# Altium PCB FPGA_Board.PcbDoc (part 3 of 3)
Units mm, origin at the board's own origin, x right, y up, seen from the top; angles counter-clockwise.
Board outline 130 x 90 mm, 4 copper layers (Component Side, Signal Layer 1, Signal Layer 2, Bottom Layer), stack 0.651 mm thick; 303 components, 175 nets, 968 pads, 775 vias.
Unrouted connection lines stored in the file: 193.
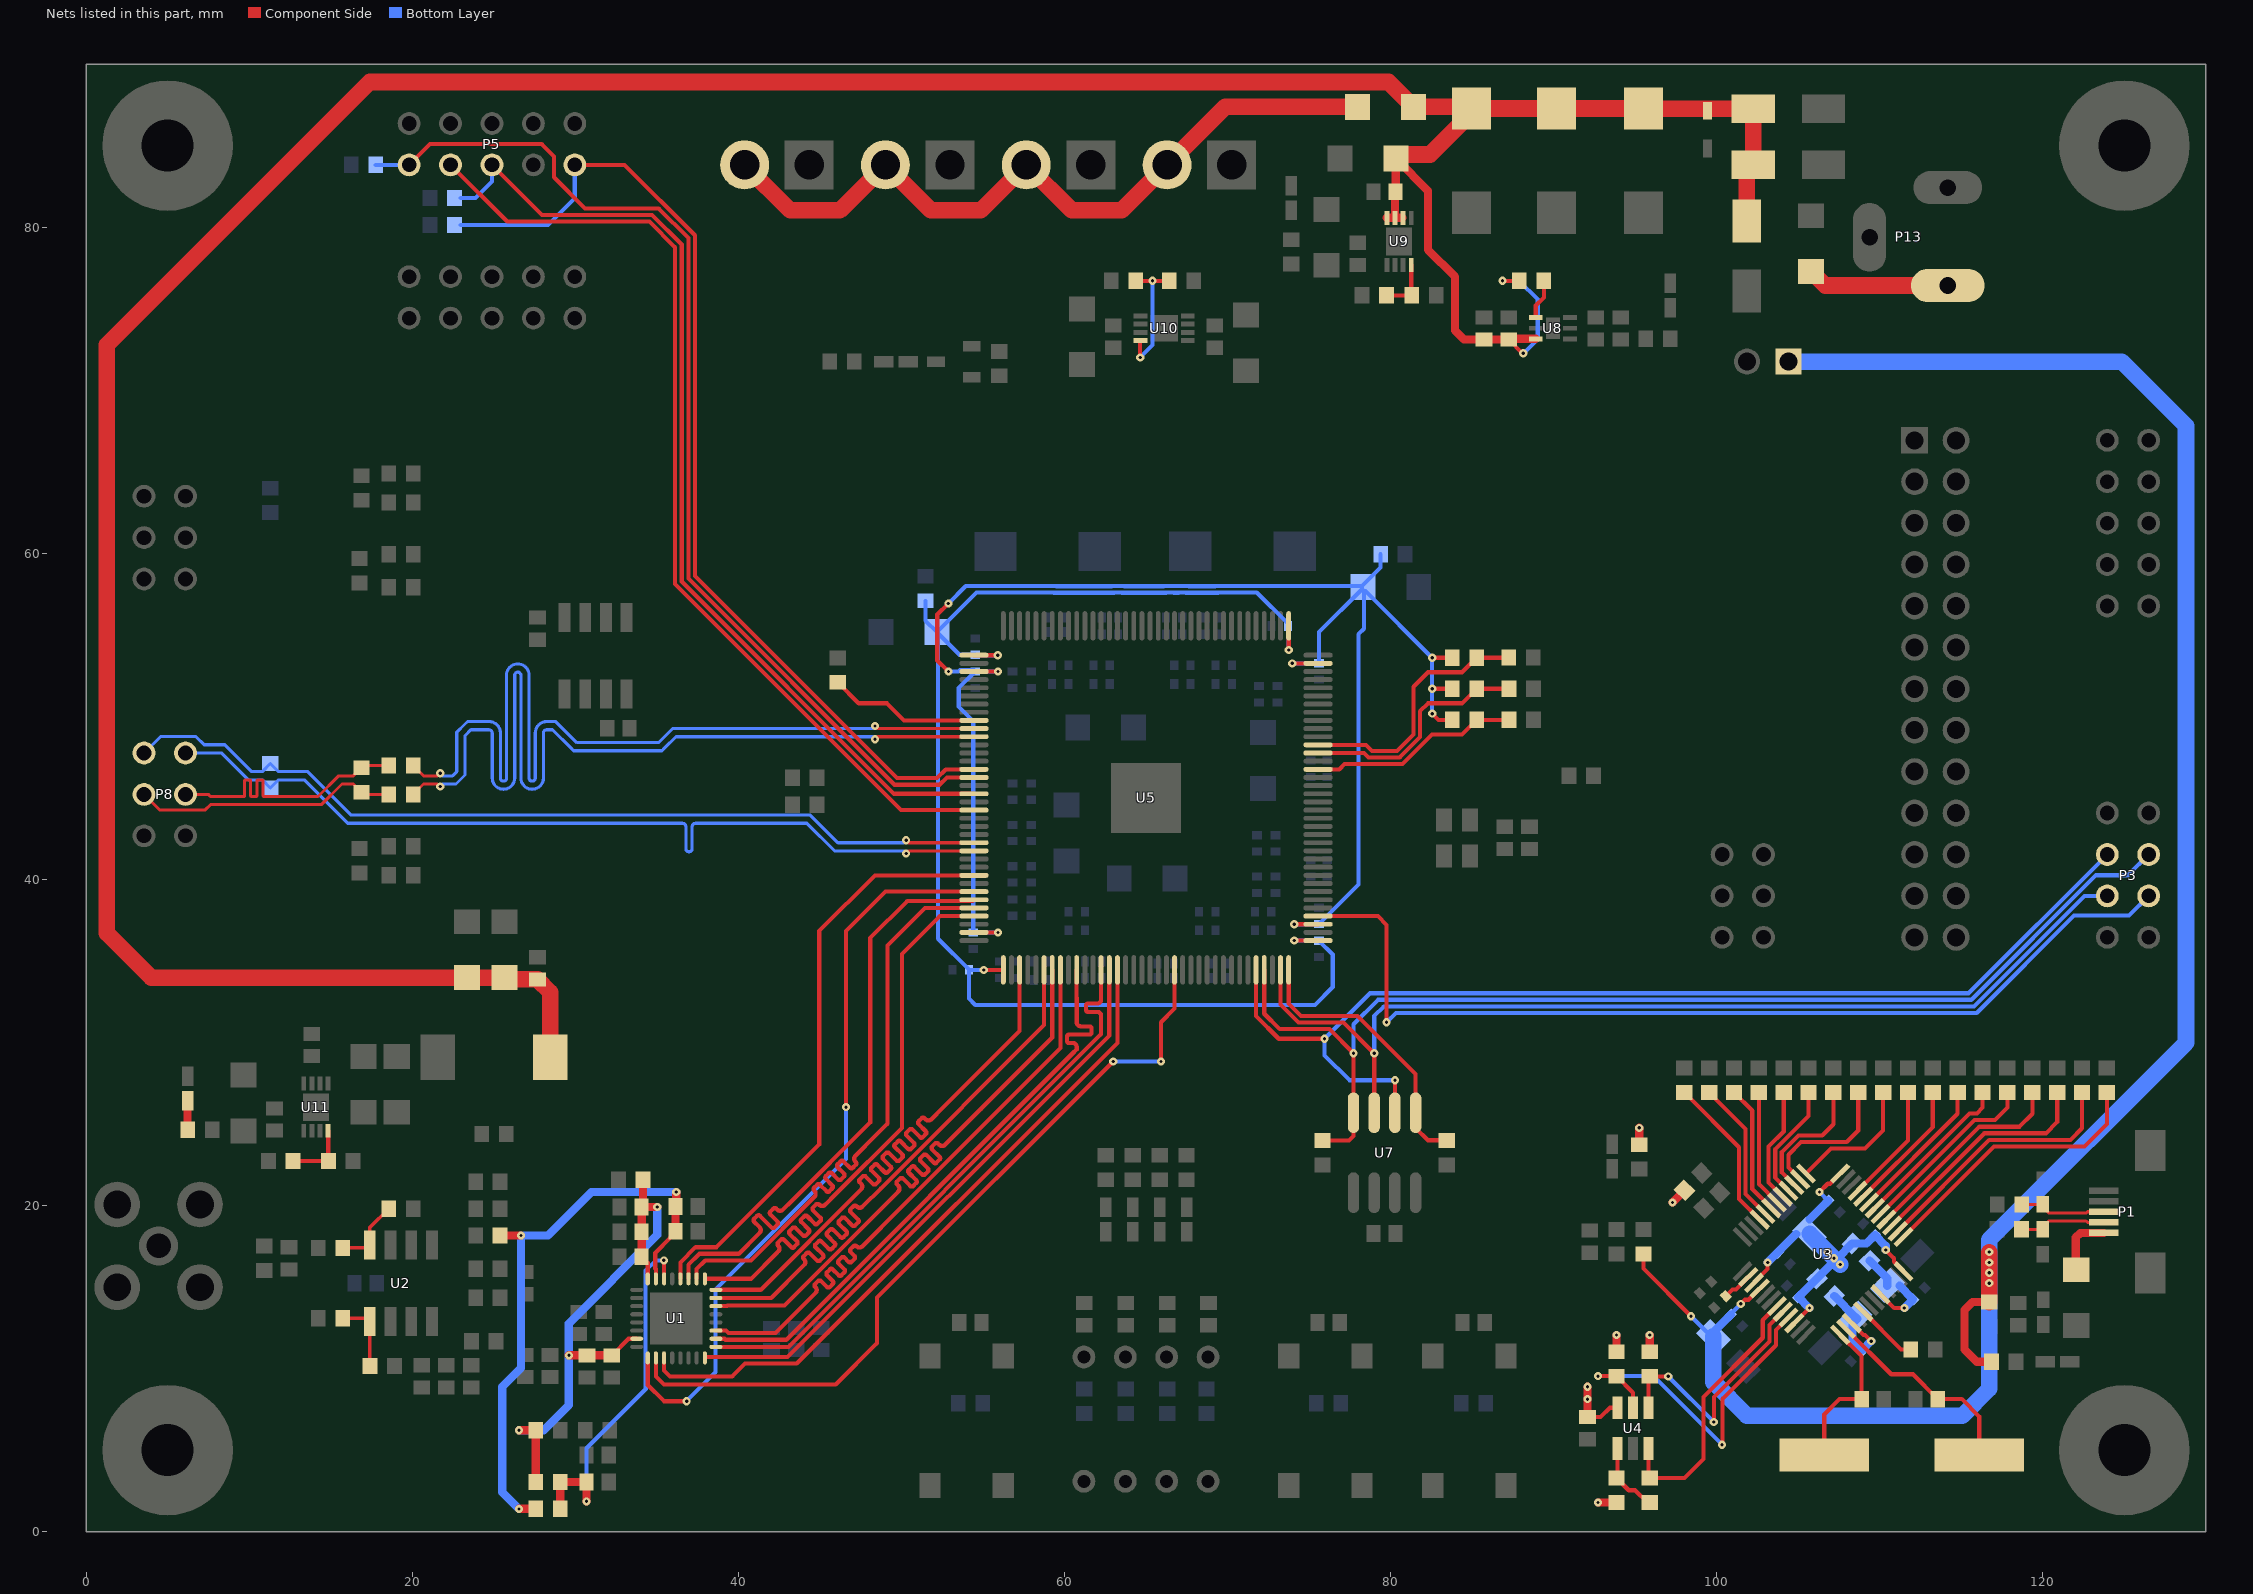
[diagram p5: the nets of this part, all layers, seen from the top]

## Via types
v1: diameter 0.5, hole 0.2, Component Side to Bottom Layer, 759 vias
v2: diameter 0.66, hole 0.33, Component Side to Bottom Layer, tented top, 16 vias

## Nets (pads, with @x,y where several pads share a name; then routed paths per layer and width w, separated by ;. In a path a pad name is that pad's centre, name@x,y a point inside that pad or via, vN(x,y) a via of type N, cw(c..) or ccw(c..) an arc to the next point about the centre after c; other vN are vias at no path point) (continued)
NetD17_1: D17.1 R94.1 | length 1.8
  Component Side w0.508: D17.1@6.223,26.428 6.223,24.65 R94.1@6.235,24.638
NetF1_1: F1.1 P1.1 | length 3.2
  Component Side w0.508: F1.1@122.014,16.696 122.014,18.034 122.298,18.318 P1.1@123.736,18.318
NetF2_2: F2.2 P11.2 P12.2 P14.2 P15.2 | length 46.1
  Component Side w1.016: P15.2@40.386,83.82 43.18,81.026 46.228,81.026 P14.2@49.022,83.82 51.816,81.026 54.864,81.026 P12.2@57.658,83.82 60.452,81.026 63.5,81.026 P11.2@66.294,83.82 69.85,87.376 F2.2@77.978,87.376 ; P12.2@58.143,83.742 P12.2@58.143,83.797
NetF3_1: F3.1 P13.1 | length 8.7
  Component Side w1.016: F3.1@105.791,77.284 106.652,76.423 P13.1@114.173,76.423
NetR1_1: R1.1 R4.2 U2.1 | length 4.5
  Component Side w0.22: R4.2@15.736,13.081 17.218,13.081 U2.1@17.399,12.9 17.399,10.172 R1.1@17.411,10.16
NetR6_2: R6.2 R8.1 U2.8 | length 4.4
  Component Side w0.22: R6.2@15.736,17.399 17.218,17.399 U2.8@17.399,17.58 17.399,18.657 R8.1@18.554,19.812
NetR18_2: R18.2 U3.5 | length 3.9
  Component Side w0.254: U3.5@108.986,13.491 111.301,11.176 R18.2@111.899,11.176
NetR19_1: R19.1 R22.1 U4.1 | length 4.5
  Component Side w0.254: U4.1@93.919,5.1 93.919,3.356 R19.1@93.853,3.29 94.603,2.54 94.996,2.54 95.746,1.79 R22.1@95.885,1.79
NetR20_1: R20.1 U3.44 U4.4 | length 15.7
  Component Side w0.254: U4.4@95.819,7.6 95.819,9.471 R20.1@95.885,9.537 95.897,9.525 v1(97.028,9.525) ; v1(99.822,6.731) 99.822,8.255 103.228,11.661 103.228,12.665 U3.44@104.054,13.491
  Bottom Layer w0.254: v1@97.155,9.525 v1(97.028,9.525) v1(99.822,6.731)
NetR21_1: R21.1 U3.45 U4.5 | length 22.3
  Component Side w0.254: v1(92.722,9.537) R21.1@93.853,9.537 94.869,8.521 U4.5@94.869,7.6 ; v1(100.33,5.334) 100.349,5.353 100.349,8.147 103.632,11.43 103.632,12.362 U3.45@104.407,13.137
  Bottom Layer w0.254: v1(92.722,9.537) 96.127,9.537 v1(100.33,5.334)
NetR22_2: R22.2 U3.43 U4.3 | length 16.9
  Component Side w0.254: U4.3@95.819,5.1 95.819,3.356 R22.2@95.885,3.29 98.032,3.29 99.187,4.445 99.187,8.255 102.824,11.892 102.824,12.968 U3.43@103.7,13.845
NetR28_1: R28.1 R34.2 U5.94 | length 13
  Component Side w0.254: U5.94@75.55,46.75 76.849,46.75 77.17,47.071 80.726,47.071 82.55,48.895 84.388,48.895 R28.1@85.277,49.784 R34.2@87.261,49.784
NetR29_1: R29.1 R35.2 U5.96 | length 14.5
  Component Side w0.254: U5.96@75.55,47.75 78.361,47.75 78.636,47.475 80.558,47.475 81.811,48.728 81.811,50.315 82.296,50.8 84.388,50.8 R29.1@85.277,51.689 R35.2@87.261,51.689
NetR30_1: R30.1 R36.2 U5.97 | length 15.9
  Component Side w0.254: U5.97@75.55,48.25 78.496,48.25 78.867,47.879 80.391,47.879 81.407,48.895 81.407,51.816 82.296,52.705 84.388,52.705 R30.1@85.277,53.594 87.223,53.594 R36.2@87.242,53.613
NetR41_2: R41.2 U3.33 | length 9.7
  Component Side w0.254: R41.2@98.011,26.936 101.371,23.576 101.371,20.399 U3.33@102.639,19.131
NetR42_2: R42.2 U3.32 | length 8.9
  Component Side w0.254: R42.2@99.535,26.936 101.775,24.696 101.775,20.702 U3.32@102.993,19.484
NetR43_2: R43.2 U3.31 | length 8
  Component Side w0.254: R43.2@101.059,26.936 102.179,25.816 102.179,21.005 U3.31@103.347,19.838
NetR44_2: R44.2 U3.30 | length 7.2
  Component Side w0.254: R44.2@102.583,26.936 102.583,21.309 U3.30@103.7,20.191
NetR45_2: R45.2 U3.29 | length 7.1
  Component Side w0.254: U3.29@104.054,20.545 103.182,21.417 103.182,23.616 104.108,24.543 104.107,24.544 R45.2@104.107,26.936
NetR51_2: R51.2 U3.28 | length 7.2
  Component Side w0.254: U3.28@104.407,20.899 103.586,21.72 103.586,23.449 105.631,25.494 R51.2@105.631,26.936
NetR54_2: R54.2 U3.27 | length 8.2
  Component Side w0.254: U3.27@104.761,21.252 103.99,22.023 103.99,23.281 105.012,24.303 106.472,24.303 107.155,24.986 R54.2@107.155,26.936
NetR55_2: R55.2 U3.26 | length 9
  Component Side w0.254: U3.26@105.114,21.606 104.394,22.326 104.394,23.114 105.179,23.899 107.973,23.899 108.679,24.605 R55.2@108.679,26.936
NetR56_2: R56.2 U3.25 | length 8.2
  Component Side w0.254: U3.25@105.468,21.959 107.004,23.495 109.093,23.495 110.203,24.605 R56.2@110.203,26.936
NetR61_2: R61.2 U3.21 | length 7.3
  Component Side w0.254: U3.21@108.633,20.899 111.727,23.993 R61.2@111.727,26.936
NetR66_2: R66.2 U3.20 | length 8.2
  Component Side w0.254: U3.20@108.986,20.545 113.251,24.81 R66.2@113.251,26.936
NetR67_2: R67.2 U3.19 | length 9
  Component Side w0.254: U3.19@109.34,20.191 114.775,25.627 R67.2@114.775,26.936
NetR68_2: R68.2 U3.18 | length 10.1
  Component Side w0.254: U3.18@109.693,19.838 115.51,25.654 115.951,25.654 116.299,26.002 R68.2@116.299,26.936
NetR71_2: R71.2 U3.17 | length 11.4
  Component Side w0.254: U3.17@110.047,19.484 115.801,25.238 117.059,25.238 117.823,26.002 R71.2@117.823,26.936
NetR75_2: R75.2 U3.16 | length 13
  Component Side w0.254: U3.16@110.401,19.131 116.104,24.834 118.56,24.834 119.355,25.629 R75.2@119.355,26.936
NetR78_2: R78.2 U3.15 | length 14.6
  Component Side w0.254: U3.15@110.754,18.777 116.407,24.43 120.188,24.43 120.879,25.121 R78.2@120.879,26.936
NetR79_2: R79.2 U3.14 | length 16.1
  Component Side w0.254: U3.14@111.108,18.424 116.71,24.026 121.689,24.026 122.403,24.74 R79.2@122.403,26.936
NetR80_2: R80.2 U3.13 | length 17.3
  Component Side w0.254: U3.13@111.461,18.07 117.013,23.622 122.555,23.622 123.927,24.994 R80.2@123.927,26.936
NetR86_1: R86.1 U8.4 | length 2.5
  Component Side w0.254: U8.4@88.9,74.452 88.9,75.184 89.408,75.692 89.408,76.696 R86.1@89.396,76.708
NetR89_1: R89.1 R91.2 U9.8 | length 3.4
  Component Side w0.254: R89.1@79.744,75.819 R91.2@81.292,75.819 81.268,75.843 U9.8@81.268,77.671
NetR90_1: R90.1 R92.2 U10.8 | length 8.1
  Component Side w0.254: R90.1@64.377,76.708 v1(65.405,76.708) R92.2@66.433,76.708 ; v1(64.643,72.009) 64.643,73.028 U10.8@64.664,73.049
  Bottom Layer w0.254: v1(64.643,72.009) 65.405,72.771 v1(65.405,76.708)
NetR95_1: R95.1 R96.2 U11.8 | length 4
  Component Side w0.254: R95.1@12.688,22.733 14.823,22.733 14.847,22.757 U11.8@14.847,24.585
NetU1_9: U1.9 U5.30 | length 46.2
  Component Side w0.254: U1.9@34.445,10.656 34.445,8.989 35.433,8.001 v1(36.83,8.001) ; v1(46.609,26.035) 46.609,36.83 49.029,39.25 U5.30@54.45,39.25
  Bottom Layer w0.254: v1(36.83,8.001) 38.608,9.779 38.608,14.859 46.609,22.86 v1(46.609,26.035)
NetU1_10: U1.10 U5.58 | length 48.1
  Component Side w0.254: U1.10@34.945,10.656 34.945,9.505 35.433,9.017 45.974,9.017 48.514,11.557 48.514,14.351 v1(62.992,28.829) ; v1(65.913,28.829) 65.913,31.242 66.75,32.079 U5.58@66.75,34.45
  Bottom Layer w0.254: v1(62.992,28.829) v1(65.913,28.829)
NetU1_11: U1.11 U5.51 | length 41.7
  Component Side w0.254: U1.11@35.445,10.656 35.445,9.894 35.814,9.525 39.624,9.525 40.405,10.306 43.58,10.306 63.25,29.976 U5.51@63.25,34.45
NetU1_16: U1.16 U5.50 | length 37
  Component Side w0.254: U1.16@37.945,10.656 37.999,10.71 43.025,10.71 62.75,30.435 U5.50@62.75,34.45
NetU1_17: U1.17 U5.49 | length 37
  Component Side w0.254: U1.17@38.62,11.331 43.075,11.331 62.25,30.506 62.25,31.496 62.25,31.623 ccw(c61.996,31.623) 61.996,31.877 61.451,31.877 cw(c61.451,32.004) 61.324,32.004 61.324,32.258 cw(c61.451,32.258) 61.451,32.385 61.996,32.385 ccw(c61.996,32.639) 62.25,32.639 62.25,33.274 U5.49@62.25,34.45
NetU1_18: U1.18 U5.46 | length 37
  Component Side w0.254: U1.18@38.62,11.831 39.147,11.831 39.209,11.769 42.941,11.769 60.509,29.337 60.75,29.578 60.75,29.718 ccw(c60.496,29.718) 60.496,29.972 60.281,29.972 cw(c60.281,30.099) 60.154,30.099 60.154,30.353 cw(c60.281,30.353) 60.281,30.48 61.525,30.48 ccw(c61.525,30.607) 61.652,30.607 61.652,30.861 ccw(c61.525,30.861) 61.525,30.988 61.004,30.988 cw(c61.004,31.242) 60.75,31.242 60.75,32.385 60.75,32.722 60.742,32.73 60.742,34.442 U5.46@60.75,34.45
NetU1_19: U1.19 U5.44 | length 37.3
  Component Side w0.254: U1.19@38.62,12.331 39.248,12.331 39.406,12.173 42.272,12.173 44.64,14.541 44.73,14.631 ccw(c44.551,14.811) 44.73,14.991 44.714,15.007 cw(c44.804,15.097) 44.714,15.187 44.893,15.366 cw(c44.983,15.276) 45.073,15.366 45.43,15.009 ccw(c45.52,15.099) 45.61,15.009 45.79,15.189 ccw(c45.7,15.278) 45.79,15.368 45.432,15.725 cw(c45.522,15.815) 45.432,15.905 45.612,16.085 cw(c45.702,15.995) 45.792,16.085 46.149,15.727 ccw(c46.239,15.817) 46.328,15.727 46.508,15.907 ccw(c46.418,15.997) 46.508,16.087 46.151,16.444 cw(c46.241,16.534) 46.151,16.623 46.33,16.803 cw(c46.42,16.713) 46.51,16.803 46.764,16.549 ccw(c46.854,16.638) 46.944,16.549 47.124,16.728 ccw(c47.034,16.818) 47.124,16.908 46.886,17.146 cw(c46.975,17.236) 46.886,17.325 47.065,17.505 cw(c47.155,17.415) 47.245,17.505 ; 47.245,17.505 ccw(c47.424,17.685) 47.604,17.505 ; 47.604,17.505 49.974,19.875 59.75,29.651 U5.44@59.75,34.45
NetU1_22: U1.22 U5.43 | length 37
  Component Side w0.254: U1.22@38.62,13.831 39.307,13.831 39.345,13.868 42.824,13.868 49.721,20.764 49.81,20.854 ccw(c49.631,21.034) 49.81,21.214 49.73,21.293 cw(c49.82,21.383) 49.73,21.473 49.91,21.653 cw(c50,21.563) 50.09,21.653 50.545,21.197 ccw(c50.635,21.287) 50.725,21.197 50.904,21.377 ccw(c50.815,21.467) 50.904,21.556 50.449,22.012 cw(c50.539,22.102) 50.449,22.191 50.628,22.371 cw(c50.718,22.281) 50.808,22.371 51.264,21.916 ccw(c51.353,22.005) 51.443,21.916 51.623,22.095 ccw(c51.533,22.185) 51.623,22.275 51.167,22.73 cw(c51.257,22.82) 51.167,22.91 51.347,23.089 cw(c51.437,23) 51.526,23.089 51.982,22.634 ccw(c52.072,22.724) 52.162,22.634 52.341,22.814 ccw(c52.251,22.903) 52.341,22.993 51.886,23.449 cw(c51.975,23.539) 51.886,23.628 52.065,23.808 cw(c52.155,23.718) 52.245,23.808 52.325,23.728 ccw(c52.504,23.908) 52.684,23.728 ; 52.684,23.728 54.864,25.908 59.25,30.294 U5.43@59.25,34.45
NetU1_23: U1.23 U5.42 | length 37.2
  Component Side w0.254: U1.23@38.62,14.331 42.017,14.331 43.942,16.256 44.032,16.346 ccw(c43.852,16.525) 44.032,16.705 44.015,16.721 cw(c44.105,16.811) 44.015,16.901 44.195,17.081 cw(c44.285,16.991) 44.375,17.081 44.83,16.625 ccw(c44.92,16.715) 45.01,16.625 45.189,16.805 ccw(c45.1,16.895) 45.189,16.984 44.734,17.44 cw(c44.824,17.53) 44.734,17.619 44.913,17.799 cw(c45.003,17.709) 45.093,17.799 45.549,17.344 ccw(c45.638,17.433) 45.728,17.344 45.908,17.523 ccw(c45.818,17.613) 45.908,17.703 45.452,18.158 cw(c45.542,18.248) 45.452,18.338 45.632,18.517 cw(c45.722,18.428) 45.811,18.517 46.267,18.062 ccw(c46.357,18.152) 46.447,18.062 46.626,18.242 ccw(c46.536,18.331) 46.626,18.421 46.171,18.877 cw(c46.26,18.967) 46.171,19.056 46.35,19.236 cw(c46.44,19.146) 46.53,19.236 46.985,18.78 ccw(c47.075,18.87) 47.165,18.78 47.345,18.96 ccw(c47.255,19.05) 47.345,19.14 46.889,19.595 cw(c46.979,19.685) 46.889,19.775 47.069,19.954 cw(c47.158,19.865) 47.248,19.954 47.265,19.938 ccw(c47.444,20.118) 47.624,19.938 48.768,21.082 58.75,31.064 U5.42@58.75,34.45
NetU1_24: U1.24 U5.39 | length 37.4
  Component Side w0.254: U1.24@38.62,14.831 41.374,14.831 47.434,20.892 47.524,20.981 ccw(c47.345,21.161) 47.524,21.341 47.444,21.42 cw(c47.534,21.51) 47.444,21.6 47.624,21.78 cw(c47.714,21.69) 47.804,21.78 48.259,21.324 ccw(c48.349,21.414) 48.439,21.324 48.618,21.504 ccw(c48.529,21.594) 48.618,21.683 48.163,22.139 cw(c48.253,22.229) 48.163,22.318 48.342,22.498 cw(c48.432,22.408) 48.522,22.498 48.978,22.043 ccw(c49.067,22.132) 49.157,22.043 49.337,22.222 ccw(c49.247,22.312) 49.337,22.402 48.881,22.857 cw(c48.971,22.947) 48.881,23.037 49.061,23.216 cw(c49.151,23.127) 49.24,23.216 49.696,22.761 ccw(c49.786,22.851) 49.876,22.761 50.055,22.941 ccw(c49.965,23.03) 50.055,23.12 49.6,23.576 cw(c49.689,23.666) 49.6,23.755 49.779,23.935 cw(c49.869,23.845) 49.959,23.935 50.414,23.479 ccw(c50.504,23.569) 50.594,23.479 50.774,23.659 ccw(c50.684,23.749) 50.774,23.839 50.318,24.294 cw(c50.408,24.384) 50.318,24.474 50.498,24.653 cw(c50.587,24.564) 50.677,24.653 51.133,24.198 ccw(c51.223,24.288) 51.312,24.198 51.492,24.377 ccw(c51.402,24.467) 51.492,24.557 51.059,24.99 cw(c51.149,25.08) 51.059,25.169 51.239,25.349 cw(c51.329,25.259) 51.418,25.349 51.476,25.292 ccw(c51.655,25.471) 51.835,25.292 52.514,25.971 57.25,30.707 U5.39@57.25,34.45
NetU1_25: U1.25 U5.33 | length 37.2
  Component Side w0.254: U1.25@37.945,15.506 40.779,15.506 42.355,17.081 42.444,17.171 ccw(c42.265,17.351) 42.444,17.531 42.428,17.547 cw(c42.518,17.637) 42.428,17.727 42.607,17.906 cw(c42.697,17.816) 42.787,17.906 43.243,17.451 ccw(c43.332,17.54) 43.422,17.451 43.602,17.63 ccw(c43.512,17.72) 43.602,17.81 43.146,18.265 cw(c43.236,18.355) 43.146,18.445 43.326,18.625 cw(c43.416,18.535) 43.506,18.625 43.961,18.169 ccw(c44.051,18.259) 44.141,18.169 44.32,18.349 ccw(c44.23,18.438) 44.32,18.528 43.865,18.984 cw(c43.955,19.074) 43.865,19.163 44.044,19.343 cw(c44.134,19.253) 44.224,19.343 44.679,18.887 ccw(c44.769,18.977) 44.859,18.887 45.039,19.067 ccw(c44.949,19.157) 45.039,19.247 44.583,19.702 cw(c44.673,19.792) 44.583,19.882 44.763,20.061 cw(c44.853,19.972) 44.942,20.061 44.959,20.045 ccw(c45.138,20.225) 45.318,20.045 ; 45.318,20.045 45.974,20.701 50.038,24.765 50.038,35.433 52.355,37.75 U5.33@54.45,37.75
NetU1_26: U1.26 U5.32 | length 37.2
  Component Side w0.254: U1.26@37.445,15.506 37.445,16.109 37.973,16.637 40.767,16.637 44.577,20.447 44.667,20.537 ccw(c44.487,20.716) 44.667,20.896 44.65,20.912 cw(c44.74,21.002) 44.65,21.092 44.83,21.272 cw(c44.92,21.182) 45.01,21.272 45.402,20.88 ccw(c45.491,20.969) 45.581,20.88 45.761,21.059 ccw(c45.671,21.149) 45.761,21.239 45.369,21.631 cw(c45.459,21.721) 45.369,21.81 45.548,21.99 cw(c45.638,21.9) 45.728,21.99 46.12,21.598 ccw(c46.21,21.688) 46.3,21.598 46.479,21.778 ccw(c46.389,21.867) 46.479,21.957 46.087,22.349 cw(c46.177,22.439) 46.087,22.529 46.267,22.708 cw(c46.357,22.619) 46.446,22.708 46.838,22.316 ccw(c46.928,22.406) 47.018,22.316 47.198,22.496 ccw(c47.108,22.586) 47.198,22.676 47.181,22.692 cw(c47.361,22.872) 47.181,23.051 48.45,24.32 49.149,25.019 49.149,35.941 51.458,38.25 U5.32@54.45,38.25
NetU1_27: U1.27 U5.31 | length 37.1
  Component Side w0.254: U1.27@36.945,15.506 36.945,16.371 37.615,17.041 40.028,17.041 41.212,18.224 41.301,18.314 ccw(c41.122,18.494) 41.301,18.674 40.967,19.007 cw(c41.057,19.097) 40.967,19.187 41.147,19.367 cw(c41.237,19.277) 41.327,19.367 42.036,18.657 ccw(c42.126,18.747) 42.216,18.657 42.395,18.837 ccw(c42.306,18.927) 42.395,19.016 41.965,19.447 cw(c42.055,19.536) 41.965,19.626 42.145,19.806 cw(c42.234,19.716) 42.324,19.806 42.379,19.751 ccw(c42.559,19.931) 42.738,19.751 43.243,20.256 48.087,25.1 48.087,36.403 50.361,38.677 54.377,38.677 U5.31@54.45,38.75
NetU1_28: U1.28 U5.28 | length 36.5
  Component Side w0.254: U1.28@36.445,15.506 36.445,16.506 37.384,17.445 38.654,17.445 44.958,23.749 44.958,36.83 48.378,40.25 U5.28@54.45,40.25
nSTATUS: R33.1 U5.9 | length 9.3
  Component Side w0.254: R33.1@46.101,52.082 47.383,50.8 49.115,50.8 50.165,49.75 U5.9@54.45,49.75
Ready_N: R52.1 U5.10 | length 58.8
  Component Side w0.19: R52.1@20.054,46.99 20.693,46.351 21.562,46.351 v1(21.717,46.506) ; v1(48.387,49.405) 48.542,49.25 U5.10@54.45,49.25
  Bottom Layer w0.19: v1(21.717,46.506) 21.872,46.351 22.479,46.351 22.733,46.605 22.733,49.022 23.241,49.53 23.387,49.676 24.716,49.676 cw(c24.716,48.986) 25.406,48.986 25.406,46.216 ccw(c25.596,46.216) 25.596,46.026 ccw(c25.596,46.216) 25.786,46.216 25.786,52.525 cw(c26.476,52.525) 26.476,53.215 cw(c26.476,52.525) 27.166,52.525 27.166,46.216 ccw(c27.356,46.216) 27.356,46.026 ccw(c27.356,46.216) 27.546,46.216 27.546,48.986 cw(c28.236,48.986) 28.236,49.676 28.81,49.676 30.099,48.387 35.107,48.387 35.97,49.25 48.232,49.25 v1(48.387,49.405)
Ready_P: R46.1 U5.11 | length 58.8
  Component Side w0.19: R46.1@20.054,45.212 20.693,45.851 21.562,45.851 v1(21.717,45.696) ; v1(48.387,48.595) 48.542,48.75 U5.11@54.45,48.75
  Bottom Layer w0.19: v1(21.717,45.696) 21.872,45.851 22.686,45.851 23.233,46.398 23.233,48.815 23.595,49.176 24.716,49.176 cw(c24.716,48.986) 24.906,48.986 24.906,46.216 ccw(c25.596,46.216) 25.596,45.526 ccw(c25.596,46.216) 26.286,46.216 26.286,52.525 cw(c26.476,52.525) 26.476,52.715 cw(c26.476,52.525) 26.666,52.525 26.666,46.216 ccw(c27.356,46.216) 27.356,45.526 ccw(c27.356,46.216) 28.046,46.216 28.046,48.986 cw(c28.236,48.986) 28.236,49.176 28.602,49.176 29.745,48.033 29.892,47.887 35.314,47.887 35.46,48.033 36.177,48.75 48.232,48.75 v1(48.387,48.595)
Ready_R_N: P8.4 R49.1 R52.2 | length 17.1
  Component Side w0.19: P8.4@6.096,45.212 7.493,45.212 7.62,45.085 9.525,45.085 9.658,45.085 ccw(c9.658,45.142) 9.715,45.142 9.715,46.028 cw(c9.772,46.028) 9.772,46.085 10.038,46.085 cw(c10.038,46.028) 10.095,46.028 10.095,45.142 ccw(c10.152,45.142) 10.152,45.085 10.418,45.085 ccw(c10.418,45.142) 10.475,45.142 10.475,46.028 cw(c10.532,46.028) 10.532,46.085 10.798,46.085 cw(c10.798,46.028) 10.855,46.028 10.855,45.142 ccw(c10.912,45.142) 10.912,45.085 10.922,45.085 14.224,45.085 15.49,46.351 16.391,46.351 R49.1@16.891,46.851 17.03,46.99 R52.2@18.554,46.99
Ready_R_P: P8.3 R46.2 R49.2 | length 16.3
  Component Side w0.19: P8.3@3.556,45.212 4.501,44.267 7.31,44.267 7.628,44.585 14.431,44.585 15.697,45.851 16.391,45.851 R49.2@16.891,45.351 17.03,45.212 R46.2@18.554,45.212
SENSE: C22.1 R12.1 R13.1 U1.30 | length 22.6
  Component Side w0.254: v1(35.433,16.637) 35.445,16.625 U1.30@35.445,15.506
  Component Side w0.508: R13.1@29.071,1.397 R12.1@29.071,3.048 C22.1@30.689,3.048 v1(30.689,1.86)
  Bottom Layer w0.254: v1(30.689,1.86) 30.689,5.115 34.32,8.746 34.32,10.264 34.313,10.271 34.313,16.007 34.943,16.637 v1(35.433,16.637)
SPI-CLK: P3.3 U5.68 U7.2 | length 68.3
  Component Side w0.254: U5.68@71.75,34.45 71.75,31.618 73.142,30.226 v1(75.946,30.226) ; U7.2@80.264,25.691 v1(80.264,27.686)
  Bottom Layer w0.254: v1(80.264,27.686) 77.47,27.686 75.946,29.21 v1(75.946,30.226) 78.74,33.02 115.443,33.02 P3.3@123.952,41.529
SPI-CS0: R83.2 U5.72 U7.1 | length 17.2
  Component Side w0.254: U5.72@73.75,34.45 73.75,32.389 74.516,31.623 77.978,31.623 81.534,28.067 U7.1@81.534,25.691 81.534,24.765 82.296,24.003 83.427,24.003 R83.2@83.439,23.991
SPI-CS1: P3.6 U5.76 | length 60.3
  Component Side w0.254: U5.76@75.55,37.75 79.217,37.75 79.756,37.211 v1(79.756,31.242)
  Bottom Layer w0.254: v1(79.756,31.242) 80.322,31.808 115.945,31.808 121.92,37.783 125.286,37.783 P3.6@126.492,38.989
SPI-MISO: P3.4 R84.2 U5.69 U7.4 | length 71.1
  Component Side w0.254: U5.69@72.25,34.45 72.25,31.763 73.198,30.815 76.246,30.815 v1(77.724,29.337) U7.4@77.724,25.691 77.724,24.257 77.458,23.991 R84.2@75.819,23.991
  Bottom Layer w0.254: v1(77.724,29.337) 77.724,31.115 79.225,32.616 115.61,32.616 123.253,40.259 125.222,40.259 P3.4@126.492,41.529
SPI-MOSI: P3.5 U5.71 U7.3 | length 63.1
  Component Side w0.254: U5.71@73.25,34.45 73.25,32.318 74.349,31.219 77.112,31.219 v1(78.994,29.337) U7.3@78.994,25.691
  Bottom Layer w0.254: v1(78.994,29.337) 78.994,31.623 79.583,32.212 115.778,32.212 122.555,38.989 P3.5@123.952,38.989
TCK: P5.1 R40.1 U5.16 | length 66.6
  Component Side w0.254: P5.1@19.812,83.82 21.082,85.09 27.94,85.09 28.702,84.328 28.702,83.058 30.607,81.153 35.116,81.153 36.934,79.335 36.934,58.442 49.571,45.805 52.345,45.805 52.79,46.25 U5.16@54.45,46.25
  Bottom Layer w0.254: R40.1@17.768,83.82 P5.1@19.812,83.82
TDI: P5.9 R39.1 U5.15 | length 62.3
  Component Side w0.254: P5.9@29.972,83.82 33.02,83.82 37.338,79.502 37.338,58.61 49.739,46.209 52.178,46.209 52.719,46.75 U5.15@54.45,46.75 U5.15@54.423,46.723
  Bottom Layer w0.254: R39.1@22.975,80.137 28.321,80.137 29.972,81.788 P5.9@29.972,83.82
TDO: P5.3 U5.20 | length 60.6
  Component Side w0.254: P5.3@22.352,83.82 25.827,80.345 34.544,80.345 36.126,78.763 36.126,58.108 49.984,44.25 U5.20@54.45,44.25
TMS: P5.5 R38.1 U5.18 | length 61
  Component Side w0.254: P5.5@24.892,83.82 27.963,80.749 34.712,80.749 36.53,78.931 36.53,58.275 49.555,45.25 U5.18@54.45,45.25
  Bottom Layer w0.254: R38.1@22.975,81.788 23.876,81.788 24.892,82.804 P5.5@24.892,83.82
TRG_N: P8.2 R48.1 U5.25 | length 54.6
  Component Side w0.19: v1(50.292,41.595) 50.447,41.75 U5.25@54.45,41.75
  Bottom Layer w0.19: P8.2@6.096,47.752 6.104,47.76 8.298,47.76 9.953,46.105 10.803,46.105 R48.1@11.303,45.605 11.803,46.105 13.386,46.105 16.049,43.442 36.195,43.442 36.39,43.442 36.585,43.442 cw(c36.585,43.247) 36.78,43.247 36.78,41.886 ccw(c36.975,41.886) 36.975,41.691 ccw(c36.975,41.886) 37.17,41.886 37.17,43.247 cw(c37.365,43.247) 37.365,43.442 37.592,43.442 44.202,43.442 45.894,41.75 50.137,41.75 v1(50.292,41.595)
TRG_P: P8.1 R48.2 U5.24 | length 54.6
  Component Side w0.19: v1(50.292,42.405) 50.447,42.25 U5.24@54.45,42.25
  Bottom Layer w0.19: P8.1@3.556,47.752 4.572,48.768 6.731,48.768 7.239,48.26 8.505,48.26 10.16,46.605 10.803,46.605 R48.2@11.303,47.105 11.803,46.605 13.593,46.605 13.716,46.482 16.256,43.942 44.409,43.942 46.101,42.25 50.137,42.25 v1(50.292,42.405)
USB_N: D1.2 P1.2 R16.1 | length 5.4
  Component Side w0.19: R16.1@118.688,18.542 119.505,18.542 119.507,18.54 D1.2@119.982,18.54 120.077,18.635 120.077,18.768 120.363,19.054 122.655,19.054 122.741,18.968 P1.2@123.736,18.968
USB_P: D2.2 P1.3 R17.1 | length 5.4
  Component Side w0.19: R17.1@118.7,20.066 119.505,20.066 119.507,20.068 D2.2@119.982,20.068 120.077,19.973 120.077,19.84 120.363,19.554 122.677,19.554 122.741,19.618 P1.3@123.736,19.618
VBUS: C23.1 C24.2 J1.1 L4.2 R23.2 R25.2 U3.40 | length 131.7
  Component Side w0.254: R25.2@95.504,17.03 95.504,16.129 v1(98.425,13.208) ; v1(101.473,13.97) 101.727,14.224 101.958,14.224 U3.40@102.639,14.905
  Component Side w0.508: L4.2@116.713,14.085 115.685,14.085 115.189,13.589 115.189,11.176 115.951,10.414 R23.2@116.852,10.414
  Component Side w1.016: L4.2@116.713,14.085 v1(116.713,15.24) v1(116.713,15.875) v1(116.713,16.51) v1(116.713,17.145)
  Bottom Layer w0.254: v1(98.425,13.208) 99.665,11.968 C23.1@99.792,11.968 ; C24.2@100.865,13.308 100.865,13.362 v1(101.473,13.97) v1@101.528,13.97
  Bottom Layer w0.508: C23.1@99.792,11.968 99.792,12.234 C24.2@100.865,13.308
  Bottom Layer w1.016: C23.1@99.792,11.968 99.792,9.174 101.854,7.112 115.062,7.112 116.713,8.763 v1(116.713,15.24) v1(116.713,15.875) v1(116.713,16.51) v1(116.713,17.145) 116.713,17.907 128.778,29.972 128.778,67.818 124.841,71.755 J1.1@104.394,71.755
VCC: C122.+ C123.+ C124.+ C125.2 C126.2 C129.2 C130.2 C137.2 C138.2 C139.2 D10.2 D11.2 D12.2 D14.2 F2.1 L8.1 R86.2 U8.6 U9.2 U9.3 U9.4 | length 219.3
  Component Side w0.254: v1(86.868,76.708) R86.2@87.896,76.708 ; C126.2@87.249,73.107 88.093,72.263 v1(88.138,72.263)
  Component Side w0.508: U9.4@79.768,80.571 U9.3@80.268,80.571 ; C129.2@80.323,84.201 80.323,82.183 C130.2@80.309,82.169 80.268,82.128 U9.3@80.268,80.571 ; C129.2@80.386,84.138 82.296,82.228 82.296,78.613 83.947,76.962 83.947,73.66 84.5,73.107 C125.2@85.725,73.107 C126.2@87.249,73.107 87.294,73.152 U8.6@88.9,73.152 ; U9.2@80.714,80.571 U9.3@80.268,80.571
  Component Side w1.016: L8.1@28.469,29.083 28.469,33.081 C139.2@27.686,33.864 25.767,33.864 C138.2@25.654,33.977 C137.2@23.368,33.977 3.996,33.977 1.27,36.703 1.27,72.771 17.399,88.9 79.874,88.9 F2.1@81.398,87.376 84.462,87.376 84.666,87.58 C124.+@84.97,87.884 ; C129.2@80.386,84.138 80.704,84.455 82.423,84.455 84.97,87.002 C124.+@84.97,87.276 ; C124.+@85.605,87.276 C123.+@90.177,87.276 C122.+@95.511,87.276 95.538,87.249 99.441,87.249 D14.2@101.482,87.249 ; D10.2@101.854,80.382 101.854,83.43 D11.2@102.244,83.82 D14.2@102.244,87.249
  Bottom Layer w0.254: v1(86.868,76.708) 87.884,76.708 89.027,75.565 89.027,73.152 v1(88.138,72.263)
VCC3V3: C28.1 C29.2 C34.2 C36.2 C37.2 C38.2 L3.2 L5.2 R15.2 R19.2 R20.2 R21.2 R24.2 U3.12 U3.24 U3.39 U3.46 U4.6 | length 31.9
  Component Side w0.254: C34.2@92.075,7.03 92.877,7.03 93.447,7.6 U4.6@93.919,7.6 ; U3.39@102.286,15.259 103.124,16.097 v1(103.124,16.51) ; U3.46@104.761,12.784 v1(105.693,13.716) ; v1(106.299,20.828) 106.807,21.336 106.949,21.336 U3.24@107.572,21.959 ; v1(110.363,17.272) 110.871,16.764 110.871,16.556 U3.12@111.461,15.966
  Component Side w0.508: C34.2@92.075,7.03 v1(92.075,8.128) v1(92.075,8.89) ; v1(92.722,1.79) R19.2@93.853,1.79 ; R21.2@93.853,11.037 v1(93.853,12.065) ; R24.2@95.25,23.737 v1(95.25,24.765) ; R20.2@95.885,11.037 v1(95.885,12.065) ; v1(97.282,20.193) R15.2@98.022,20.933
  Bottom Layer w0.254: v1(105.693,13.716) v1@105.791,13.716 ; v1(106.299,20.828) C37.2@106.834,20.293
  Bottom Layer w0.508: v1(103.124,16.51) C28.1@104.872,18.258 ; v1(105.693,13.716) 105.664,13.716 C38.2@105.002,14.378 106.266,15.643 L3.2@106.277,15.643 ; 105.694,19.152 C37.2@106.834,20.293 ; L3.2@106.15,15.516 L3.2@106.277,15.643 ; v1(110.363,17.272) 110.363,17.526 C36.2@109.701,18.188 109.187,17.675 L5.2@108.309,17.675 107.397,16.764 v1(107.188,16.764) 107.188,16.555 L3.2@106.277,15.643
  Bottom Layer w1.016: C28.1@105.694,18.258 v1(106.807,17.145) v1(107.188,16.764) v1(107.569,16.383)
VCC_PLL: C112.2 C115.2 C117.2 C119.2 C121.2 L6.2 U5.1 U5.37 U5.73 U5.109 | length 88.9
  Component Side w0.254: U5.1@54.45,53.75 v1(55.909,53.75) ; v1(55.052,34.45) U5.37@56.25,34.45 ; v1(73.75,54.065) U5.109@73.75,55.55 ; v1(74.096,36.25) U5.73@75.55,36.25
  Bottom Layer w0.254: L6.2@51.482,57.082 51.482,55.859 C112.2@52.176,55.165 ; v1(55.052,34.45) 54.155,34.45 C115.2@54.141,34.464 ; v1(55.909,53.75) 54.556,53.75 C119.2@54.53,53.776 53.565,53.776 C112.2@52.244,55.097 ; v1(73.75,54.065) 73.75,55.495 C117.2@73.699,55.546 73.699,55.681 71.791,57.589 69.417,57.589 69.406,57.578 67.451,57.578 67.44,57.589 67.004,57.589 66.993,57.578 66.705,57.578 66.686,57.597 66.25,57.597 66.231,57.578 63.514,57.578 63.503,57.589 63.067,57.589 63.056,57.578 59.339,57.578 59.328,57.589 54.6,57.589 C112.2@52.176,55.165 ; v1(74.096,36.25) 75.596,36.25 C121.2@75.612,36.234 76.454,35.392 76.454,33.401 75.358,32.305 54.53,32.305 54.141,32.694 C115.2@54.141,34.464 ; C112.2@52.176,55.165 C112.2@52.244,55.097 ; C112.2@52.244,55.097 52.244,36.361 C115.2@54.141,34.464
VCCA: C113.2 C114.2 C116.2 C118.2 C120.2 L7.1 R28.2 R29.2 R30.2 U5.3 U5.35 U5.75 U5.107 | length 104.3
  Component Side w0.254: v1(52.879,56.927) 52.197,56.245 52.197,53.434 v1(52.887,52.744) ; U5.35@54.45,36.75 v1(55.927,36.75) ; U5.3@54.45,52.75 v1(55.925,52.75) ; v1(73.971,53.25) U5.107@75.55,53.25 ; v1(74.096,37.25) U5.75@75.55,37.25 ; v1(82.55,50.165) 82.931,49.784 R28.2@83.777,49.784 ; v1(82.55,51.689) R29.2@83.777,51.689 ; v1(82.55,53.594) R30.2@83.777,53.594
  Bottom Layer w0.254: v1(52.879,56.927) 53.945,57.993 59.496,57.993 59.507,57.982 62.888,57.982 62.899,57.993 63.671,57.993 63.682,57.982 66.063,57.982 66.082,58.001 67.6,58.001 67.619,57.982 69.238,57.982 69.249,57.993 C113.2@78.242,57.993 ; v1(52.887,52.744) 53.506,52.744 53.594,52.832 54.454,52.832 C118.2@54.536,52.75 ; v1(55.925,52.75) C118.2@54.536,52.75 ; v1(55.927,36.75) 54.411,36.75 C114.2@54.403,36.742 54.403,49.704 53.514,50.593 53.514,51.728 C118.2@54.53,52.744 C118.2@54.536,52.75 ; v1(73.971,53.25) 75.61,53.25 C116.2@75.612,53.252 75.612,55.165 C113.2@78.242,57.795 ; v1(74.096,37.25) 75.596,37.25 C120.2@75.612,37.266 78.025,39.679 78.025,55.038 78.359,55.372 C113.2@78.359,57.678 ; L7.1@79.387,59.944 79.387,59.138 C113.2@78.242,57.993 ; v1(82.55,50.165) v1(82.55,51.689) v1(82.55,53.594) 78.466,57.678 C113.2@78.359,57.678 ; C113.2@78.242,57.795 C113.2@78.242,57.993 ; C113.2@78.242,57.795 C113.2@78.359,57.678
VCM: C10.2 C11.2 R2.2 R13.2 U1.31 | length 36.6
  Component Side w0.254: U1.31@34.945,15.506 34.945,16.109 34.906,16.148 34.906,17.096 35.842,18.032 35.842,18.107 C11.2@36.15,18.415
  Component Side w0.508: R2.2@25.388,18.161 v1(26.67,18.161) ; v1(26.543,1.397) R13.2@27.571,1.397 R13.2@27.698,1.397 ; C11.2@36.15,18.415 C10.2@36.15,19.939 36.195,19.984 v1(36.195,20.828)
  Bottom Layer w0.508: v1(26.543,1.397) 25.527,2.413 25.527,8.89 26.67,10.033 v1(26.67,18.161) 28.321,18.161 30.988,20.828 v1(36.195,20.828)
VCORE: C35.2 U3.38 | length 1.9
  Component Side w0.254: C35.2@100.557,14.451 100.965,14.859 101.179,14.859 U3.38@101.932,15.612
VDD: C1.1 C2.1 C4.1 C6.1 C9.1 L1.1 R11.2 R12.2 U1.7 U1.32 | length 34.3
  Component Side w0.254: C9.1@32.246,10.812 33.265,11.831 U1.7@33.77,11.831 ; C4.1@34.069,16.863 34.445,16.487 U1.32@34.445,15.506
  Component Side w0.508: v1(26.543,6.223) R11.2@27.571,6.223 R12.2@27.571,3.175 ; R12.2@27.571,2.794 27.571,2.921 R12.2@27.679,2.813 ; v1(29.608,10.812) C6.1@30.722,10.812 C9.1@32.246,10.812 ; C4.1@34.069,16.863 C2.1@34.069,18.387 C1.1@34.069,19.911 ; L1.1@34.151,21.59 34.151,19.993 C1.1@34.069,19.911 ; v1(35.024,19.911) C1.1@34.069,19.911
  Bottom Layer w0.508: v1(26.543,6.223) 28.067,6.223 29.608,7.764 v1(29.608,10.812) 29.608,12.772 35.024,18.188 v1(35.024,19.911)
VPHY: C25.1 C26.2 L3.1 U3.3 | length 6.9
  Component Side w0.254: U3.3@108.279,12.784 108.998,12.065 109.093,12.065 v1(109.474,11.684) v1@109.379,11.684
  Bottom Layer w0.254: v1@109.347,11.684 v1(109.474,11.684)
  Bottom Layer w0.508: L3.1@107.21,14.456 108.521,13.144 108.615,13.051 108.582,13.018 108.331,12.767 108.331,11.756 C26.2@108.939,11.149 v1(109.474,11.684)
VPLL: C30.1 C31.2 L5.1 U3.8 | length 5.7
  Component Side w0.254: U3.8@110.047,14.552 110.883,13.716 v1(111.506,13.716)
  Bottom Layer w0.508: L5.1@109.369,16.615 110.46,15.524 C30.1@110.46,15.083 ; C30.1@111.21,15.083 C31.2@112.041,14.251 v1(111.506,13.716)
XI: C39.2 U3.1 Y1.1 | length 9.7
  Component Side w0.254: Y1.1@106.596,4.699 106.596,7.188 107.536,8.128 C39.2@108.888,8.128 108.888,10.761 U3.1@107.572,12.077
XO: C40.2 U3.2 Y1.2 | length 12.8
  Component Side w0.254: U3.2@107.926,12.43 110.704,9.652 112.026,9.652 C40.2@113.55,8.128 115.029,8.128 116.096,7.061 Y1.2@116.096,4.699
pads on no net: P1.4 P5.6 P5.7 P5.8 U1.12 U1.13 U1.14 U1.15 U2.7 U5.101 U5.126 U5.127 U5.128 U5.129 U7.6 U7.7 U8.2 U8.5

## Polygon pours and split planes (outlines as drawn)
+3V3 on Signal Layer 2 "Signal2 Layer-+3V3" (solid, shelved, pour order 84): 0,90 130,90 130,0 0,0
+3V-A on Signal Layer 2 "Signal2 Layer-GND" (solid, shelved, pour order 76): 0,32.766 24.765,32.766 24.765,23.241 25.527,22.479 39.624,22.479 39.624,18.034 36.068,18.034 36.068,14.986 34.163,14.986 34.163,0 0,0
+2V5 on Signal Layer 2 "Signal2 Layer-+2V5" (solid, shelved, pour order 36): 84.455,78.105 98.425,78.105 98.425,70.485 87.63,70.485 87.63,59.182 81.153,59.182 81.153,60.833 84.455,60.833 84.455,71.12
+1V2 on Signal Layer 2 "Signal2 Layer-+1V2" (solid, shelved, pour order 28): 55.88,35.814 73.834,35.814 73.834,43.675 70.18,43.675 70.18,46.977 74.295,46.977 74.295,55.626 58.547,55.626 58.547,58.674 64.77,58.674 64.77,69.85 73.025,69.85 73.025,77.47 50.546,77.47 50.546,47.244 50.559,47.231 61.341,47.231 61.341,41.23 60.973,40.767 55.88,40.767
VCC3V3 on Signal Layer 2 "Signal2 Layer-+VCC3V3" (solid, shelved, pour order 40): 130,0 130,28.829 89.662,28.829 89.662,0
GND on Bottom Layer "BOT Layer-GND" (solid, shelved, pour order 80): 0,90 130,90 130,0 0,0
AGND on Bottom Layer "BOT Layer-AGND" (solid, shelved, pour order 72): 0,32.766 24.765,32.766 24.765,23.241 25.527,22.479 39.624,22.479 39.624,18.034 36.068,18.034 36.068,14.986 34.163,14.986 34.163,0 0,0
+3V3 on Bottom Layer "BOT Layer-+3V3" (solid, shelved, pour order 64): 70.993,62.611 77.343,62.611 77.343,57.404 70.993,57.404
+1V2 on Bottom Layer "BOT Layer-+1V2" (solid, shelved, pour order 62): 62.611,47.498 58.801,47.498 58.801,51.435 62.611,51.435
+1V2 on Bottom Layer "BOT Layer-+1V2" (solid, shelved, pour order 60): 61.595,41.91 61.595,38.354 64.77,38.354 64.77,41.91
+3V3 on Bottom Layer "BOT Layer-+3V3" (solid, shelved, pour order 58): 58.42,46.355 58.42,43.053 61.722,43.053 61.722,46.355
+3V3 on Bottom Layer "BOT Layer-+3V3" (solid, shelved, pour order 56): 73.914,46.863 73.914,43.815 70.104,43.815 70.104,46.863
+1V2 on Bottom Layer "BOT Layer-+1V2" (solid, shelved, pour order 38): 50.546,57.589 58.547,57.589 58.547,62.484 52.959,62.484 50.546,60.071
+1V2 on Bottom Layer "BOT Layer-+1V2" (solid, shelved, pour order 34): 65.024,41.783 65.024,38.227 61.722,38.227 61.722,41.783
+1V2 on Bottom Layer "BOT Layer-+1V2" (solid, shelved, pour order 32): 62.484,47.244 58.674,47.244 58.674,51.054 62.484,51.054
GND on Component Side "TOP Layer-GND" (solid, shelved, pour order 78): 0,90 130,90 130,0 0,0
AGND on Component Side "TOP Layer-GND" (solid, shelved, pour order 70): 0,32.766 24.765,32.766 24.765,23.241 25.527,22.479 39.624,22.479 39.624,18.034 36.068,18.034 36.068,14.986 34.163,14.986 34.163,0 0,0
GND on Signal Layer 1 "Signal1 Layer-GND" (solid, shelved, pour order 82): 0,90 130,90 130,0 0,0
AGND on Signal Layer 1 "Signal1 Layer-AGND" (solid, shelved, pour order 74): 0,32.766 24.765,32.766 24.765,23.241 25.527,22.479 39.624,22.479 39.624,18.034 36.068,18.034 36.068,14.986 34.163,14.986 34.163,0 0,0

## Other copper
Signal Layer 2:
  pour cut-out: 105.953,21.207 106.715,21.207 106.715,20.445 105.953,20.445
  pour cut-out: 110.017,17.651 110.779,17.651 110.779,16.889 110.017,16.889
  pour cut-out: 105.347,14.095 106.109,14.095 106.109,13.333 105.347,13.333
  pour cut-out: 102.778,16.889 103.54,16.889 103.54,16.127 102.778,16.127
  pour cut-out: 39.655,13.71 40.417,13.71 40.417,12.948 39.655,12.948
  pour cut-out: 40.675,13.714 41.437,13.714 41.437,12.952 40.675,12.952
  pour cut-out: 55.534,46.099 56.296,46.099 56.296,45.337 55.534,45.337
  pour cut-out: 55.534,52.129 56.296,52.129 56.296,51.367 55.534,51.367
  pour cut-out: 58.404,54.43 59.166,54.43 59.166,53.668 58.404,53.668
  pour cut-out: 59.344,54.354 60.106,54.354 60.106,53.592 59.344,53.592
  pour cut-out: 60.904,54.412 61.666,54.412 61.666,53.65 60.904,53.65
  pour cut-out: 62.904,54.358 63.666,54.358 63.666,53.596 62.904,53.596
  pour cut-out: 65.904,54.437 66.666,54.437 66.666,53.675 65.904,53.675
  pour cut-out: 66.904,54.421 67.666,54.421 67.666,53.659 66.904,53.659
  pour cut-out: 69.297,54.401 70.059,54.401 70.059,53.639 69.297,53.639
  pour cut-out: 70.059,54.401 70.821,54.401 70.821,53.639 70.059,53.639
  pour cut-out: 73.712,51.129 74.474,51.129 74.474,50.367 73.712,50.367
  pour cut-out: 73.64,46.629 74.402,46.629 74.402,45.867 73.64,45.867
  pour cut-out: 73.488,42.209 74.25,42.209 74.25,41.447 73.488,41.447
  pour cut-out: 73.671,40.629 74.433,40.629 74.433,39.867 73.671,39.867
  pour cut-out: 73.488,39.161 74.25,39.161 74.25,38.399 73.488,38.399
  pour cut-out: 72.298,36.447 73.06,36.447 73.06,35.685 72.298,35.685
  pour cut-out: 68.361,36.32 69.123,36.32 69.123,35.558 68.361,35.558
  pour cut-out: 67.472,36.32 68.234,36.32 68.234,35.558 67.472,35.558
  pour cut-out: 65.404,36.323 66.166,36.323 66.166,35.561 65.404,35.561
  pour cut-out: 60.904,36.356 61.666,36.356 61.666,35.594 60.904,35.594
  pour cut-out: 55.962,36.494 56.724,36.494 56.724,35.732 55.962,35.732
  pour cut-out: 55.581,38.018 56.343,38.018 56.343,37.256 55.581,37.256
  pour cut-out: 55.533,40.129 56.295,40.129 56.295,39.367 55.533,39.367
  pour cut-out: 55.636,41.629 56.398,41.629 56.398,40.867 55.636,40.867
  pour cut-out: 59.904,36.362 60.666,36.362 60.666,35.6 59.904,35.6
  pour cut-out: 57.404,36.322 58.166,36.322 58.166,35.56 57.404,35.56

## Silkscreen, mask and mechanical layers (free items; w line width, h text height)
Top Overlay:
  lines w0.22: 40.259,63.754 89.408,63.754
  lines w0.254: 0.508,22.098 8.128,22.098 9.506,20.72 17.164,20.72 19.304,22.86 48.26,22.86 48.26,0.762 ; 0.508,35.56 17.272,35.56 21.082,39.37 29.21,39.37 33.02,35.56 33.02,22.86 ; 39.37,73.66 44.704,68.326 96.266,68.326 99.695,71.755 99.695,79.629 ; 48.26,15.24 48.26,17.018 56.388,17.018 58.42,19.05 58.42,27.178 71.628,27.178 71.628,19.05 73.66,17.018 89.662,17.018 89.662,15.24 ; 89.662,0.508 89.662,30.48 129.032,30.48
  text "+3V3 OK" at 75.184,84.836 h0.8 r90
  text "JTAG" at 13.97,82.296 h1 r90
  text "POWER +5V" at 119.888,75.438 h1.3
  text "4x +5V Power Output" at 37.846,74.422 h1.2
  text "AS" at 13.97,74.168 h1 r90
  text "+1V2 OK" at 45.974,72.898 h0.8
  text "+2V5 OK" at 99.06,72.39 h0.8 r90
  text "Voltage Regulators" at 74.93,69.088 h0.8
  text "Power USB" at 99.568,67.056 h1
  text "Particle Physics DAQ Education Kit" at 40.386,64.008 h1.5
  text "FPGA Board" at 77.216,61.722 h1.2
  text "GPIO-1" at 120.65,58.674 h1 r90
  text "LVDS / Input/Output-2" at 13.208,53.34 h1 r90
  text "GPIO-2" at 108.458,49.53 h1 r90
  text "LVDS / Input/Output-1" at 13.208,37.592 h1 r90
  text "SPI" at 120.396,36.83 h1 r90
  text "UART" at 97.028,35.56 h1 r90
  text "Voltage Regulator / Analog" at 0.508,32.004 h0.8
  text "FTDI" at 90.17,28.702 h1
  text "+3V-A OK" at 1.016,26.162 h0.8
  text "User LEDs" at 60.198,24.13 h1
  text "+3V3-USB OK" at 92.71,20.066 h0.8 r90
  text "User SWITCHs" at 58.928,15.24 h1
  text "Reset" at 82.296,13.97 h1
  text "User BTN-1" at 51.816,13.716 h0.9
  text "User BTN-2" at 73.152,13.716 h0.9
  text "Signal Input" at 0.508,10.922 h1
  text "V-USB OK" at 122.682,9.906 h0.8
  text "Analog To Digital / Converter" at 10.16,1.27 h0.8
Mechanical 1:
  lines w2.4: -1.2,12.4 -1.2,-1.2 12.4,-1.2 ; -1.2,18.5 -1.2,33.1 ; -1.2,38.3 -1.2,52.9 ; -1.2,57.9 -1.2,72.5 ; -1.2,77.6 -1.2,91.2 12.4,91.2 ; 16.9,91.2 37.1,91.2 ; 17.1,-1.2 37.3,-1.2 ; 42,-1.2 62.2,-1.2 ; 42,91.2 62.2,91.2 ; 67.8,-1.2 88,-1.2 ; 67.8,91.2 88,91.2 ; 92.7,91.2 112.9,91.2 ; 92.9,-1.2 113.1,-1.2 ; 117.6,-1.2 131.2,-1.2 131.2,12.4 ; 117.6,91.2 131.2,91.2 131.2,77.6 ; 131.2,17.5 131.2,32.1 ; 131.2,37.1 131.2,51.7 ; 131.2,56.9 131.2,71.5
